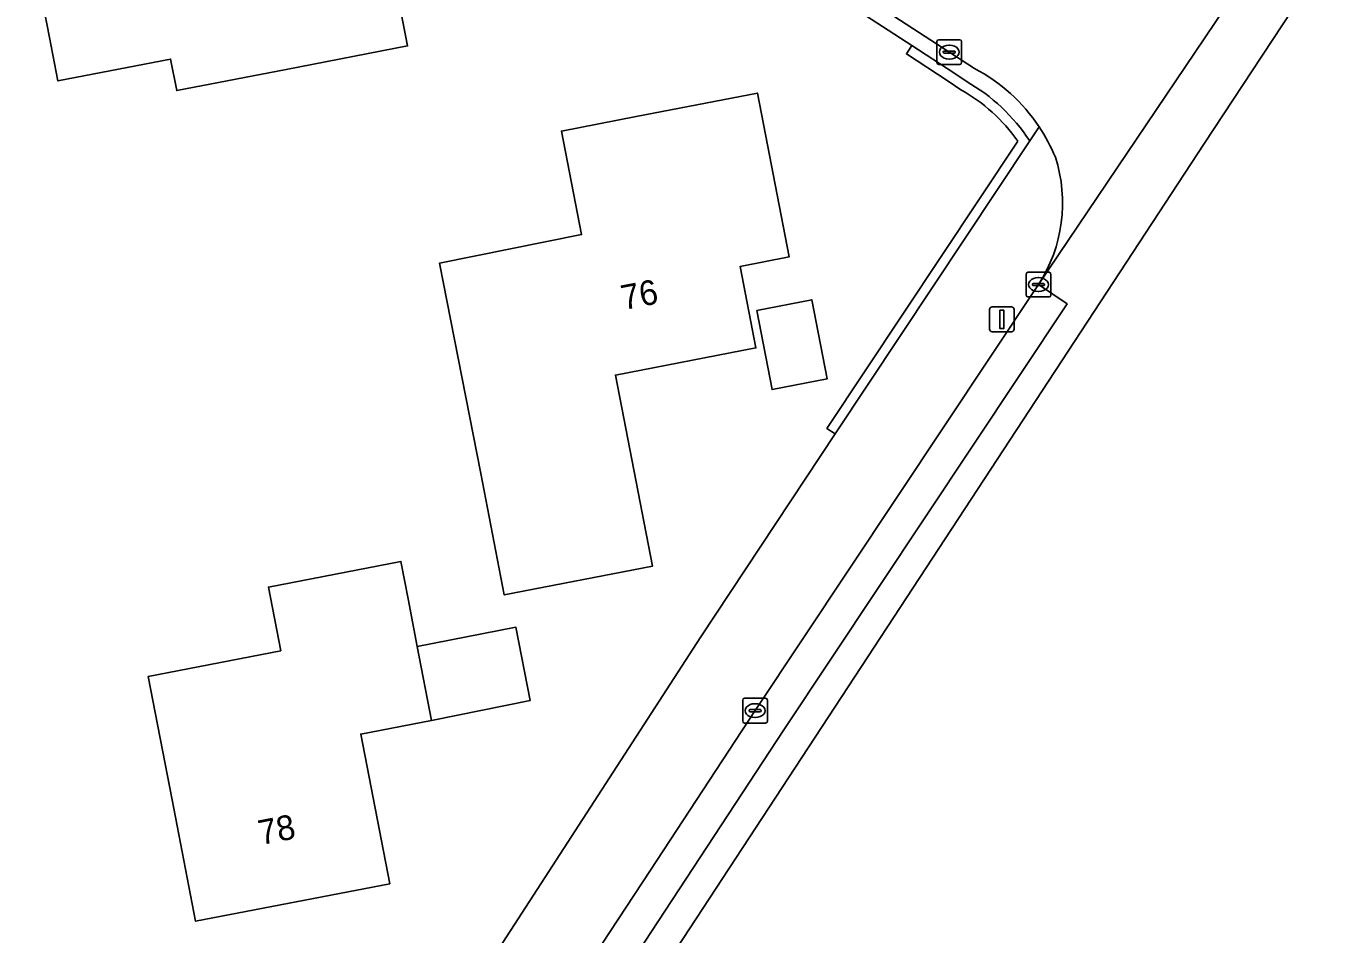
# Model space of a CAD drawing. Extents: x 157648 to 158502, y 379212 to 380938.
# Drawn here: x 158355.4 to 158407.7, y 380434.7 to 380471.4 of the extents above; entities that cross this region are included whole.
import ezdxf

# ---------------------------------------------------------------- set-up
doc = ezdxf.new("R2010")
doc.units = 0
for name, color, linetype in [('IMGEO_Erf', 7, 'Continuous'), ('IMGEO_Groenvoorziening', 7, 'Continuous'), ('IMGEO_Haag', 7, 'Continuous'), ('IMGEO_Hek', 7, 'Continuous'), ('IMGEO_Kolk', 7, 'Continuous'), ('IMGEO_Lichtmast', 7, 'Continuous'), ('IMGEO_Pand', 7, 'Continuous'), ('IMGEO_Pand_nummerreeks', 7, 'Continuous'), ('IMGEO_Rijbaan_lokaal_gesloten', 7, 'Continuous'), ('IMGEO_Rijbaan_lokaal_open', 7, 'Continuous'), ('IMGEO_Voetpad_open', 7, 'Continuous')]:
    doc.layers.add(name, color=color, linetype=linetype)

msp = doc.modelspace()

# ---------------------------------------------------------------- linework, layer by layer
at = {"layer": 'IMGEO_Erf'}
for points in [[(158393.178, 380468.812), (158392.666, 380469.161), (158390.971, 380470.261), (158391.189, 380470.597), (158388.589, 380472.285), (158388.371, 380471.949), (158378.189, 380478.557), (158378.407, 380478.893), (158367.597, 380485.882), (158366.984, 380486.274), (158365.946, 380486.942)], [(158388.093, 380454.893), (158387.76, 380455.114), (158395.476, 380466.737)], [(158310.642, 380438.099), (158310.18, 380437.339), (158314.722, 380432.862), (158316.188, 380431.36), (158320.425, 380427.602), (158325.031, 380424.307), (158329.956, 380421.512), (158334.859, 380419.373), (158336.058, 380422.023), (158339.44, 380420.493), (158338.355, 380418.094), (158338.382, 380418.084), (158344.183, 380415.454), (158349.677, 380412.232), (158356.951, 380407.019), (158382.664, 380446.693), (158388.093, 380454.893)]]:
    msp.add_lwpolyline(points, dxfattribs=at)
for points in [[(158356.657, 380469.164), (158356.316, 380470.924), (158355.366, 380475.832), (158356.639, 380476.078), (158356.016, 380479.298), (158363.906, 380480.825), (158364.296, 380478.811), (158363.688, 380478.694), (158363.926, 380477.467), (158365.124, 380477.699), (158366.105, 380472.634), (158369.993, 380473.387), (158369.789, 380474.442), (158370.042, 380474.491), (158370.799, 380470.582), (158365.891, 380469.632), (158361.463, 380468.775), (158361.217, 380470.047)], [(158373.759, 380453.295), (158372.087, 380461.794), (158377.833, 380462.952), (158377.022, 380467.141), (158380.04, 380467.726), (158384.948, 380468.676), (158386.23, 380462.049), (158384.251, 380461.666), (158384.888, 380458.374), (158379.206, 380457.275), (158380.702, 380449.546), (158374.709, 380448.386)], [(158384.921, 380459.888), (158387.144, 380460.318), (158387.763, 380457.12), (158385.54, 380456.69)], [(158365.169, 380448.704), (158370.527, 380449.741), (158370.821, 380448.223), (158371.193, 380446.304), (158375.182, 380447.076), (158375.756, 380444.111), (158371.772, 380443.314), (158368.905, 380442.759), (158370.076, 380436.709), (158362.228, 380435.19), (158361.278, 380440.099), (158360.312, 380445.088), (158365.668, 380446.125)]]:
    msp.add_lwpolyline(points, close=True, dxfattribs=at)
msp.add_arc((158389.686, 380462.634), 7.096, 35.3189, 60.5196, dxfattribs=at)
at = {"layer": 'IMGEO_Groenvoorziening'}
for points in [[(158392.888, 380469.494), (158391.189, 380470.597), (158390.971, 380470.261), (158392.666, 380469.161), (158393.178, 380468.812)], [(158393.39, 380469.152), (158392.888, 380469.494)], [(158395.476, 380466.737), (158387.76, 380455.114), (158388.093, 380454.893), (158395.958, 380466.74)]]:
    msp.add_lwpolyline(points, dxfattribs=at)
for centre, radius, start, end in [((158389.686, 380462.634), 7.096, 35.3189, 60.5196), ((158389.69, 380462.64), 7.49, 33.1908, 60.3977)]:
    msp.add_arc(centre, radius, start, end, dxfattribs=at)
at = {"layer": 'IMGEO_Haag'}
for points in [[(158391.189, 380470.597), (158390.971, 380470.261), (158392.666, 380469.161), (158393.178, 380468.812)], [(158393.39, 380469.152), (158392.888, 380469.494), (158391.189, 380470.597)], [(158395.476, 380466.737), (158387.76, 380455.114), (158388.093, 380454.893), (158395.958, 380466.74)]]:
    msp.add_lwpolyline(points, dxfattribs=at)
for centre, radius, start, end in [((158389.686, 380462.634), 7.096, 35.3189, 60.5196), ((158389.69, 380462.64), 7.49, 33.1908, 60.3977)]:
    msp.add_arc(centre, radius, start, end, dxfattribs=at)
at = {"layer": 'IMGEO_Hek'}
for points in [[(158388.589, 380472.285), (158391.189, 380470.597)], [(158388.093, 380454.893), (158382.664, 380446.693)]]:
    msp.add_lwpolyline(points, dxfattribs=at)
at = {"layer": 'IMGEO_Kolk'}
for p, q in [((158392.204, 380469.906), (158392.204, 380470.758)), ((158392.279, 380470.832), (158393.131, 380470.832)), ((158393.205, 380470.758), (158393.205, 380469.906)), ((158392.463, 380470.326), (158392.463, 380470.338)), ((158392.901, 380470.289), (158392.503, 380470.289)), ((158392.506, 380470.375), (158392.904, 380470.375)), ((158392.692, 380470.612), (158392.717, 380470.612)), ((158392.947, 380470.338), (158392.947, 380470.326)), ((158393.131, 380469.832), (158392.279, 380469.832)), ((158392.715, 380470.052), (158392.69, 380470.052)), ((158395.812, 380460.508), (158395.812, 380461.36)), ((158395.887, 380461.434), (158396.739, 380461.434)), ((158396.813, 380461.36), (158396.813, 380460.508)), ((158396.071, 380460.928), (158396.071, 380460.94)), ((158396.509, 380460.891), (158396.111, 380460.891)), ((158396.114, 380460.977), (158396.512, 380460.977)), ((158396.3, 380461.214), (158396.325, 380461.214)), ((158396.555, 380460.94), (158396.555, 380460.928)), ((158396.739, 380460.434), (158395.887, 380460.434)), ((158396.323, 380460.654), (158396.298, 380460.654)), ((158384.352, 380443.28), (158384.352, 380444.132)), ((158384.427, 380444.206), (158385.279, 380444.206)), ((158385.353, 380444.132), (158385.353, 380443.28)), ((158384.611, 380443.7), (158384.611, 380443.712)), ((158385.049, 380443.663), (158384.651, 380443.663)), ((158384.654, 380443.749), (158385.052, 380443.749)), ((158384.84, 380443.986), (158384.865, 380443.986)), ((158385.095, 380443.712), (158385.095, 380443.7)), ((158385.279, 380443.206), (158384.427, 380443.206)), ((158384.863, 380443.426), (158384.838, 380443.426))]:
    msp.add_line(p, q, dxfattribs=at)
for points in [[(158392.204, 380469.906), (158392.204, 380470.758)], [(158392.279, 380470.832), (158393.131, 380470.832)], [(158393.205, 380470.758), (158393.205, 380469.906)], [(158393.131, 380469.832), (158392.279, 380469.832)], [(158395.812, 380460.508), (158395.812, 380461.36)], [(158395.887, 380461.434), (158396.739, 380461.434)], [(158396.813, 380461.36), (158396.813, 380460.508)], [(158396.739, 380460.434), (158395.887, 380460.434)], [(158384.352, 380443.28), (158384.352, 380444.132)], [(158384.427, 380444.206), (158385.279, 380444.206)], [(158385.353, 380444.132), (158385.353, 380443.28)], [(158385.279, 380443.206), (158384.427, 380443.206)]]:
    msp.add_lwpolyline(points, dxfattribs=at)
for centre, radius, start, end in [((158392.281, 380470.756), 0.0765, 91.552, 178.448), ((158392.281, 380470.756), 0.0765, 91.552, 178.448), ((158393.129, 380470.756), 0.0765, 1.552, 88.448), ((158393.129, 380470.756), 0.0765, 1.552, 88.448), ((158392.503, 380470.335), 0.0403, 85.8775, 175.7526), ((158392.5, 380470.325), 0.0366, 178.938, 274.7102), ((158392.904, 380470.332), 0.043, 264.8664, 352.4533), ((158392.908, 380470.337), 0.0386, 1.7309, 96.639), ((158392.281, 380469.908), 0.0765, 181.552, 268.448), ((158392.281, 380469.908), 0.0765, 181.552, 268.448), ((158393.129, 380469.908), 0.0765, 271.552, 358.448), ((158393.129, 380469.908), 0.0765, 271.552, 358.448), ((158395.889, 380461.358), 0.0765, 91.552, 178.448), ((158395.889, 380461.358), 0.0765, 91.552, 178.448), ((158396.737, 380461.358), 0.0765, 1.552, 88.448), ((158396.737, 380461.358), 0.0765, 1.552, 88.448), ((158396.111, 380460.937), 0.0403, 85.8775, 175.7526), ((158396.108, 380460.927), 0.0366, 178.938, 274.7102), ((158396.512, 380460.934), 0.043, 264.8664, 352.4533), ((158396.516, 380460.939), 0.0386, 1.7309, 96.639), ((158395.889, 380460.51), 0.0765, 181.552, 268.448), ((158395.889, 380460.51), 0.0765, 181.552, 268.448), ((158396.737, 380460.51), 0.0765, 271.552, 358.448), ((158396.737, 380460.51), 0.0765, 271.552, 358.448), ((158384.429, 380444.13), 0.0765, 91.552, 178.448), ((158384.429, 380444.13), 0.0765, 91.552, 178.448), ((158385.277, 380444.13), 0.0765, 1.552, 88.448), ((158385.277, 380444.13), 0.0765, 1.552, 88.448), ((158384.651, 380443.709), 0.0403, 85.8775, 175.7526), ((158384.648, 380443.699), 0.0366, 178.938, 274.7102), ((158385.052, 380443.706), 0.043, 264.8664, 352.4533), ((158385.056, 380443.711), 0.0386, 1.7309, 96.639), ((158384.429, 380443.282), 0.0765, 181.552, 268.448), ((158384.429, 380443.282), 0.0765, 181.552, 268.448), ((158385.277, 380443.282), 0.0765, 271.552, 358.448), ((158385.277, 380443.282), 0.0765, 271.552, 358.448)]:
    msp.add_arc(centre, radius, start, end, dxfattribs=at)
for centre, major_axis, ratio, start_param, end_param in [((158392.691, 380470.332), (-0.387, 0.002), 0.722429, 4.712389, 7.853982), ((158392.716, 380470.332), (-0.39, 0.002), 0.717154, 1.570796, 4.712389), ((158396.299, 380460.934), (-0.387, 0.002), 0.722429, 4.712389, 7.853982), ((158396.324, 380460.934), (-0.39, 0.002), 0.717154, 1.570796, 4.712389), ((158384.839, 380443.706), (-0.387, 0.002), 0.722429, 4.712389, 7.853982), ((158384.864, 380443.706), (-0.39, 0.002), 0.717154, 1.570796, 4.712389)]:
    msp.add_ellipse(centre, major_axis=major_axis, ratio=ratio, start_param=start_param, end_param=end_param, dxfattribs=at)
at = {"layer": 'IMGEO_Lichtmast'}
for p, q in [((158394.336, 380459.127), (158394.336, 380459.927)), ((158394.336, 380459.927), (158394.336, 380459.127)), ((158394.436, 380460.027), (158395.226, 380460.027)), ((158395.226, 380460.027), (158394.436, 380460.027)), ((158395.326, 380459.927), (158395.326, 380459.127)), ((158395.326, 380459.127), (158395.326, 380459.927)), ((158395.226, 380459.027), (158394.436, 380459.027)), ((158394.436, 380459.027), (158395.226, 380459.027))]:
    msp.add_line(p, q, dxfattribs=at)
msp.add_lwpolyline([(158394.756, 380459.902), (158394.906, 380459.902), (158394.906, 380459.152), (158394.756, 380459.152), (158394.756, 380459.902)], dxfattribs=at)
for centre, start, end in [((158394.436, 380459.927), 90, 180), ((158394.436, 380459.927), 90, 180), ((158395.226, 380459.927), 0, 90), ((158395.226, 380459.927), 360, 90), ((158394.436, 380459.127), 180, 270), ((158394.436, 380459.127), 180, 270), ((158395.226, 380459.127), 270, 0), ((158395.226, 380459.127), 270, 0)]:
    msp.add_arc(centre, 0.1, start, end, dxfattribs=at)
at = {"layer": 'IMGEO_Pand'}
for points in [[(158364.296, 380478.811), (158363.906, 380480.825), (158356.016, 380479.298), (158356.639, 380476.078), (158355.366, 380475.832), (158356.316, 380470.924), (158356.657, 380469.164), (158361.217, 380470.047), (158361.463, 380468.775), (158365.891, 380469.632), (158370.799, 380470.582), (158370.042, 380474.491), (158369.789, 380474.442), (158369.993, 380473.387), (158366.105, 380472.634), (158365.124, 380477.699), (158363.926, 380477.467), (158363.688, 380478.694)], [(158380.04, 380467.726), (158377.022, 380467.141), (158377.833, 380462.952), (158372.087, 380461.794), (158373.759, 380453.295), (158374.709, 380448.386), (158380.702, 380449.546), (158379.206, 380457.275), (158384.888, 380458.374), (158384.251, 380461.666), (158386.23, 380462.049), (158384.948, 380468.676)], [(158384.921, 380459.888), (158385.54, 380456.69), (158387.763, 380457.12), (158387.144, 380460.318)], [(158368.905, 380442.759), (158371.772, 380443.314), (158371.193, 380446.304), (158370.821, 380448.223), (158370.527, 380449.741), (158365.169, 380448.704), (158365.668, 380446.125), (158360.312, 380445.088), (158361.278, 380440.099), (158362.228, 380435.19), (158370.076, 380436.709)], [(158371.193, 380446.304), (158371.772, 380443.314), (158375.756, 380444.111), (158375.182, 380447.076)]]:
    msp.add_lwpolyline(points, close=True, dxfattribs=at)
at = {"layer": 'IMGEO_Rijbaan_lokaal_gesloten'}
for points in [[(158407.741, 380473.826), (158407.007, 380474.3), (158405.828, 380475.061), (158396.313, 380460.934), (158397.472, 380460.149), (158386.021, 380442.934), (158375.308, 380426.619), (158359.212, 380401.425)], [(158321.913, 380335.046), (158322.556, 380335.707), (158323.969, 380337.301), (158322.8, 380338.281), (158325.582, 380341.817), (158354.457, 380386.687), (158358.544, 380392.841), (158366.85, 380405.76), (158366.882, 380405.811), (158366.882, 380405.811), (158364.309, 380407.61), (158389.416, 380445.887), (158403.005, 380466.605), (158407.741, 380473.826)], [(158375.308, 380426.619), (158386.021, 380442.934), (158397.472, 380460.149), (158396.313, 380460.934), (158384.854, 380443.705), (158380.617, 380437.253), (158376.38, 380430.8), (158374.16, 380427.419), (158368.874, 380419.368), (158366.413, 380415.445), (158363.995, 380411.592), (158361.927, 380408.296), (158354.389, 380396.614), (158353.953, 380395.948), (158348.618, 380387.799), (158348.419, 380387.488), (158346.168, 380384.007), (158332.685, 380363.158), (158330.179, 380359.3), (158327.688, 380355.467), (158321.705, 380346.258)]]:
    msp.add_lwpolyline(points, dxfattribs=at)
at = {"layer": 'IMGEO_Rijbaan_lokaal_open'}
for points in [[(158370.478, 380491.685), (158367.307, 380486.782), (158379.676, 380478.787), (158393.724, 380469.669)], [(158396.313, 380460.934), (158405.828, 380475.061), (158406.243, 380475.678)]]:
    msp.add_lwpolyline(points, dxfattribs=at)
for centre, radius, start, end in [((158390.391, 380463.345), 7.149, 33.7149, 62.2066), ((158390.407, 380463.352), 7.131, 22.5089, 33.7423), ((158391.233, 380464.226), 6.054, 327.0558, 17.8512)]:
    msp.add_arc(centre, radius, start, end, dxfattribs=at)
at = {"layer": 'IMGEO_Voetpad_open'}
for points in [[(158379.676, 380478.787), (158367.307, 380486.782), (158366.984, 380486.274), (158367.597, 380485.882), (158378.407, 380478.893), (158388.589, 380472.285), (158391.189, 380470.597), (158392.888, 380469.494), (158393.39, 380469.152)], [(158393.724, 380469.669), (158379.676, 380478.787)], [(158396.337, 380467.313), (158395.958, 380466.74), (158388.093, 380454.893), (158382.664, 380446.693), (158356.951, 380407.019), (158354.764, 380403.614), (158353.642, 380401.727), (158351.3, 380398.128), (158318.204, 380347.27), (158316.304, 380344.56)], [(158395.958, 380466.74), (158396.337, 380467.313)], [(158363.995, 380411.592), (158366.413, 380415.445), (158368.874, 380419.368), (158374.16, 380427.419), (158376.38, 380430.8), (158380.617, 380437.253), (158384.854, 380443.705), (158396.313, 380460.934)]]:
    msp.add_lwpolyline(points, dxfattribs=at)
for centre, radius, start, end in [((158390.391, 380463.345), 7.149, 33.7149, 62.2066), ((158389.69, 380462.64), 7.49, 33.1908, 60.3977), ((158390.407, 380463.352), 7.131, 22.5089, 33.7423), ((158391.233, 380464.226), 6.054, 327.0558, 17.8512)]:
    msp.add_arc(centre, radius, start, end, dxfattribs=at)

# ---------------------------------------------------------------- texts
at = {"layer": 'IMGEO_Pand_nummerreeks'}
for s, rotation, p in [('76', 10.9469, (158379.534, 380459.898)), ('78', 10.955, (158364.865, 380438.267))]:
    msp.add_text(s, height=1, rotation=rotation, dxfattribs=at).set_placement(p)

doc.saveas('drawing.dxf')
